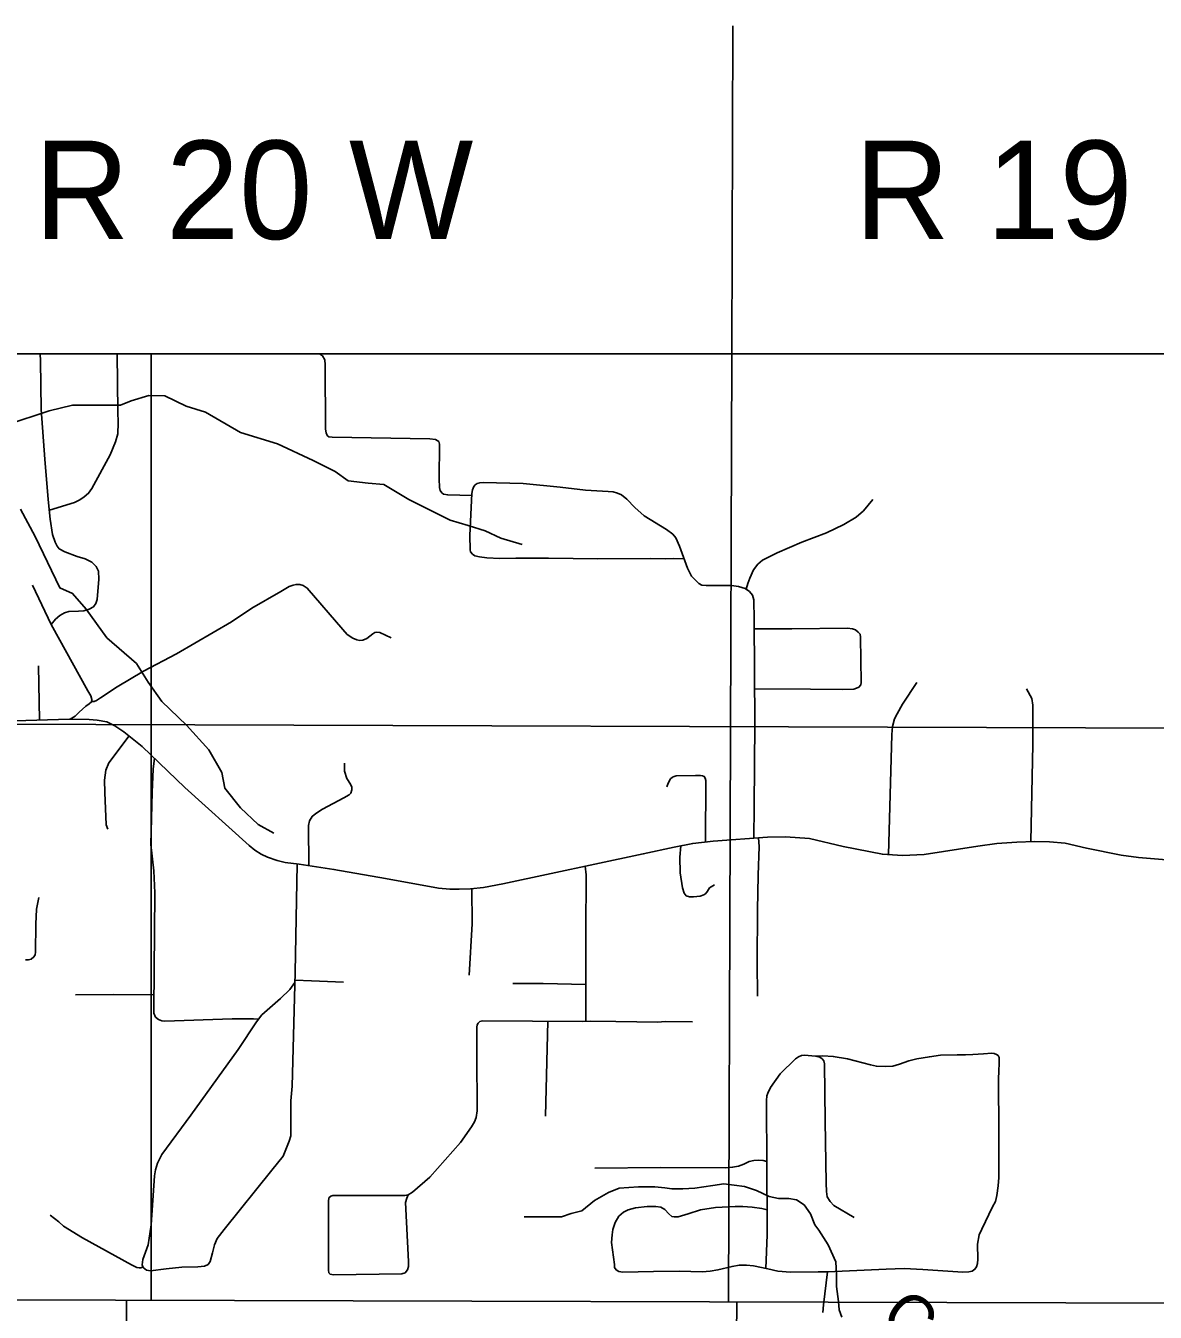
# Model space of a CAD drawing. Extents: x 1374139 to 1377472, y 1168351 to 1170484.
# Drawn here: x 1375576.5 to 1375783.1, y 1169404.2 to 1169639.4 of the extents above; entities that cross this region are included whole.
import ezdxf

# ---------------------------------------------------------------- set-up
doc = ezdxf.new("R2010")
doc.units = 0
for name, color, linetype in [('14', 7, 'Continuous'), ('26', 7, 'Continuous'), ('Default', 7, 'Continuous')]:
    doc.layers.add(name, color=color, linetype=linetype)

msp = doc.modelspace()

# ---------------------------------------------------------------- linework, layer by layer
at = {"layer": '14'}
msp.add_line((1375705.84, 1169639.43), (1375705.62, 1169579.43), dxfattribs=at)
at = {"layer": '26'}
msp.add_lwpolyline([(1375090, 1169579.43), (1376597.43, 1169579.43), (1376597.43, 1168653.79), (1375090, 1168653.79)], close=True, dxfattribs=at)
at = {"layer": 'Default'}
for p, q in [((1375812.86, 1169510.92), (1375090, 1169513.23)), ((1375941.96, 1169405.45), (1375090, 1169407.73))]:
    msp.add_line(p, q, dxfattribs=at)
for points in [[(1375579.17, 1169579.43), (1375579.21, 1169578.12), (1375579.32, 1169569.28), (1375579.99, 1169560.18), (1375580.63, 1169552.81), (1375581, 1169549.17), (1375581.43, 1169546.37), (1375581.88, 1169544.98), (1375582.24, 1169544.28), (1375582.62, 1169543.79), (1375583.68, 1169543.2), (1375585.9, 1169542.35), (1375587.39, 1169541.92), (1375588.58, 1169541.31), (1375589.39, 1169540.57), (1375589.8, 1169539.69), (1375589.89, 1169538.21), (1375589.57, 1169534.53), (1375589.34, 1169533.79), (1375588.92, 1169533.19), (1375588.09, 1169532.74), (1375587.14, 1169532.45), (1375586.18, 1169532.38), (1375584.4, 1169532.33), (1375583.62, 1169532.09), (1375582.77, 1169531.57), (1375581.96, 1169530.92), (1375581.19, 1169529.96)], [(1375580.83, 1169550.86), (1375585.41, 1169552.22), (1375586.38, 1169552.73), (1375587.21, 1169553.27), (1375588.01, 1169553.95), (1375588.62, 1169554.78), (1375591.94, 1169560.99), (1375592.95, 1169563.33), (1375593.34, 1169564.78), (1375593.42, 1169566.83), (1375593.38, 1169568.89), (1375593.23, 1169579.43)], [(1375599.47, 1169579.43), (1375599.44, 1169406.37)], [(1375658.08, 1169553.51), (1375653.67, 1169553.62), (1375652.93, 1169553.75), (1375652.62, 1169553.99), (1375652.31, 1169554.43), (1375652.15, 1169554.99), (1375652.12, 1169556.6), (1375652.18, 1169562.93), (1375652.03, 1169563.37), (1375651.72, 1169563.61), (1375651.41, 1169563.74), (1375650.38, 1169563.86), (1375632.55, 1169564.17), (1375631.96, 1169564.23), (1375631.65, 1169564.51), (1375631.43, 1169565.01), (1375631.31, 1169565.66), (1375631.28, 1169577.42), (1375631.19, 1169578.32), (1375630.78, 1169579.04), (1375630.21, 1169579.43)], [(1375705.62, 1169579.43), (1375704.99, 1169406.09)], [(1375615.8, 1169565.07), (1375609.4, 1169568.76), (1375605.82, 1169569.87), (1375601.93, 1169571.73), (1375599.04, 1169571.81), (1375595.81, 1169570.86), (1375593.87, 1169570.06)], [(1375593.87, 1169570.06), (1375591.89, 1169570.06), (1375588.66, 1169570.06), (1375585.07, 1169570.06), (1375580.77, 1169568.98), (1375573.05, 1169566.47)], [(1375654.14, 1169549.02), (1375651.31, 1169550.44), (1375646.56, 1169552.8), (1375641.98, 1169555.52), (1375639.1, 1169555.78), (1375635.49, 1169556.2), (1375633.1, 1169557.92), (1375629.08, 1169559.94), (1375622.52, 1169562.95), (1375615.8, 1169565.07)], [(1375709.68, 1169490.84), (1375709.71, 1169496.58), (1375709.83, 1169511.85), (1375709.71, 1169530.76), (1375709.63, 1169534.47), (1375709.42, 1169535.3), (1375708.88, 1169535.96), (1375708.06, 1169536.5), (1375706.84, 1169536.9), (1375705.58, 1169537.04), (1375703.52, 1169537.04), (1375700.95, 1169537.06), (1375700.15, 1169537.14), (1375699.57, 1169537.44), (1375698.27, 1169538.75), (1375697.51, 1169540.23), (1375696.05, 1169544.26), (1375695.39, 1169545.78), (1375694.81, 1169546.46), (1375693.71, 1169547.28), (1375689.58, 1169549.79), (1375687.9, 1169551.31), (1375686.42, 1169552.85), (1375685.44, 1169553.67), (1375684.71, 1169553.97), (1375683.93, 1169554.17), (1375683.01, 1169554.25), (1375680.93, 1169554.35), (1375678.89, 1169554.51), (1375674.26, 1169555.07), (1375667.47, 1169555.72), (1375660.15, 1169555.9), (1375659.52, 1169555.86), (1375659.06, 1169555.72), (1375658.7, 1169555.5), (1375658.42, 1169555.17), (1375658.2, 1169554.59), (1375658.1, 1169553.91), (1375657.98, 1169551.31), (1375657.74, 1169546.18), (1375657.78, 1169543.56), (1375657.86, 1169543.2), (1375658.18, 1169542.8), (1375658.64, 1169542.48), (1375659.5, 1169542.28), (1375660.85, 1169542.14), (1375663.19, 1169541.98), (1375666.13, 1169542.06), (1375672.12, 1169542.04), (1375681.11, 1169541.92), (1375690.78, 1169541.98), (1375693.58, 1169541.94), (1375694.9, 1169541.98), (1375696.89, 1169541.92)], [(1375731.4, 1169552.82), (1375729.7, 1169550.73), (1375728.38, 1169549.59), (1375726.12, 1169548.21), (1375722.96, 1169546.72), (1375718.42, 1169545.02), (1375713.92, 1169543.03), (1375711.26, 1169541.69), (1375710.41, 1169540.98), (1375709.56, 1169539.95), (1375708.92, 1169538.42), (1375708.57, 1169537.43), (1375708.23, 1169536.39)], [(1375575.56, 1169551.03), (1375578.25, 1169546), (1375582.74, 1169536.66), (1375585.07, 1169535.58), (1375587.59, 1169532.71), (1375591.36, 1169527.5), (1375596.74, 1169522.83), (1375598.89, 1169519.42), (1375601.41, 1169515.83), (1375605.89, 1169511.52), (1375610.02, 1169507.03), (1375612.35, 1169502.9), (1375612.89, 1169500.03), (1375615.76, 1169496.44), (1375618.99, 1169493.38), (1375621.87, 1169491.77)], [(1375667.31, 1169544.55), (1375663.36, 1169545.7), (1375660.5, 1169547.09), (1375657.44, 1169548.01), (1375654.14, 1169549.02)], [(1375581.19, 1169529.96), (1375577.77, 1169537.1)], [(1375643.32, 1169527.49), (1375641.27, 1169528.49), (1375640.72, 1169528.55), (1375640.33, 1169528.46), (1375639.96, 1169528.22), (1375638.87, 1169527.4), (1375638.18, 1169527.1), (1375637.6, 1169527.04), (1375637.03, 1169527.13), (1375636.33, 1169527.43), (1375635.3, 1169528.13), (1375634.52, 1169529.04), (1375627.98, 1169536.58), (1375627.25, 1169537.09), (1375626.65, 1169537.25), (1375625.95, 1169537.28), (1375625.41, 1169537.15), (1375624.71, 1169536.91), (1375623.17, 1169535.97), (1375617.84, 1169532.95), (1375614.12, 1169530.43), (1375604.1, 1169524.56), (1375598.05, 1169521.41), (1375593.26, 1169518.53), (1375590.2, 1169516.55), (1375589.48, 1169516.06), (1375589.05, 1169515.88), (1375588.54, 1169515.85)], [(1375581.19, 1169529.96), (1375587.84, 1169517.79), (1375588.39, 1169516.88), (1375588.57, 1169516.23), (1375588.54, 1169515.81), (1375588.12, 1169515.4), (1375587.53, 1169515.02), (1375586.29, 1169513.88), (1375585.56, 1169513.2), (1375584.66, 1169512.61)], [(1375709.72, 1169529.15), (1375713.75, 1169529.14), (1375716.57, 1169529.14), (1375726.8, 1169529.26), (1375727.67, 1169529.17), (1375728.26, 1169528.95), (1375728.73, 1169528.52), (1375729.07, 1169528.15), (1375729.13, 1169527.59), (1375729.25, 1169519.33), (1375729.19, 1169518.88), (1375728.88, 1169518.47), (1375728.45, 1169518.29), (1375727.95, 1169518.13), (1375725.78, 1169518.04), (1375720.01, 1169518.1), (1375709.79, 1169518.16)], [(1375578.87, 1169522.38), (1375579.02, 1169512.47)], [(1375734.3, 1169487.84), (1375734.87, 1169509.81), (1375735.03, 1169511.26), (1375735.4, 1169512.69), (1375735.87, 1169513.63), (1375736.83, 1169515.36), (1375739.47, 1169519.3)], [(1375759.51, 1169518.17), (1375760.47, 1169516.4), (1375760.64, 1169515.17), (1375760.64, 1169507.98), (1375760.31, 1169490.23)], [(1375574.59, 1169512.35), (1375584.48, 1169512.61), (1375588.12, 1169512.55), (1375589.56, 1169512.45), (1375591.36, 1169512.11), (1375592.8, 1169511.41), (1375594.47, 1169510.31), (1375597.81, 1169507.63), (1375605.59, 1169500.15), (1375617.35, 1169489.52), (1375618.42, 1169488.68), (1375619.59, 1169487.92), (1375620.73, 1169487.38), (1375622.5, 1169486.81), (1375623.93, 1169486.44), (1375626.51, 1169486.08), (1375632.85, 1169485.14), (1375642.28, 1169483.47), (1375652, 1169481.7), (1375654.04, 1169481.53), (1375655.74, 1169481.53), (1375657.85, 1169481.6), (1375660.22, 1169481.87), (1375663.76, 1169482.53), (1375689.42, 1169487.98), (1375695.06, 1169489.19), (1375698.47, 1169489.89), (1375702.21, 1169490.29), (1375712.17, 1169491.02), (1375715.47, 1169491.12), (1375719.85, 1169490.79), (1375725.96, 1169489.35), (1375733.17, 1169487.92), (1375736.84, 1169487.68), (1375740.78, 1169487.88), (1375750.62, 1169489.39), (1375754.1, 1169489.89), (1375757.77, 1169490.15), (1375760.99, 1169490.25), (1375763.7, 1169490.19), (1375766.6, 1169489.92), (1375770.51, 1169489.02), (1375776.83, 1169487.75), (1375780, 1169487.31), (1375789.42, 1169486.54)], [(1375595.42, 1169509.55), (1375591.69, 1169504.61), (1375591.17, 1169503.32), (1375590.92, 1169501.48), (1375590.96, 1169499.2), (1375591.22, 1169493.33), (1375591.52, 1169492.51)], [(1375619.07, 1169457.77), (1375618.14, 1169457.85), (1375614.24, 1169457.85), (1375601.94, 1169457.43), (1375601.42, 1169457.47), (1375600.78, 1169457.73), (1375600.22, 1169458.16), (1375599.96, 1169458.84), (1375599.96, 1169459.57), (1375600.13, 1169480.85), (1375599.92, 1169484.88), (1375599.41, 1169489.72), (1375599.62, 1169499.25), (1375599.79, 1169503.49), (1375600.06, 1169505.47)], [(1375628.3, 1169485.81), (1375628.22, 1169493.2), (1375628.39, 1169494.06), (1375628.86, 1169494.83), (1375629.55, 1169495.39), (1375630.75, 1169496.16), (1375634.69, 1169498.22), (1375635.63, 1169498.78), (1375635.98, 1169499.12), (1375636.15, 1169499.72), (1375636.15, 1169500.19), (1375635.89, 1169500.71), (1375635.25, 1169501.78), (1375634.82, 1169503.11), (1375634.82, 1169503.97), (1375634.82, 1169504.57)], [(1375700.81, 1169490.14), (1375700.87, 1169501.38), (1375700.78, 1169501.83), (1375700.59, 1169502.13), (1375700.26, 1169502.28), (1375699.87, 1169502.34), (1375698.97, 1169502.31), (1375695.45, 1169502.24), (1375695.11, 1169502.13), (1375694.8, 1169501.99), (1375694.44, 1169501.69), (1375693.97, 1169500.91), (1375693.75, 1169500.28)], [(1375696.28, 1169489.44), (1375696.13, 1169487.38), (1375696.19, 1169484.5), (1375696.63, 1169481.8), (1375696.93, 1169480.79), (1375697.29, 1169480.29), (1375697.89, 1169480.11), (1375698.6, 1169480.11), (1375699.83, 1169480.27), (1375700.52, 1169480.5), (1375700.86, 1169480.73), (1375701.18, 1169481.18), (1375701.55, 1169481.78), (1375702.48, 1169482.33)], [(1375710.5, 1169490.9), (1375710.62, 1169489.37), (1375710.42, 1169484.08), (1375710.3, 1169477.69), (1375710.26, 1169468.17), (1375710.34, 1169462)], [(1375626.13, 1169486.13), (1375625.79, 1169466.3), (1375625.24, 1169445.51), (1375624.97, 1169442.86), (1375625, 1169437.35), (1375625, 1169436.42), (1375624.69, 1169435.43), (1375623.56, 1169432.71), (1375621.53, 1169430.13), (1375612.79, 1169419.32), (1375611.52, 1169417.63), (1375611, 1169416.49), (1375610.69, 1169415.02), (1375610.25, 1169413.43), (1375609.87, 1169412.88), (1375609.21, 1169412.61), (1375608.01, 1169412.47), (1375605.06, 1169412.43), (1375602.21, 1169412.12), (1375599.35, 1169411.75), (1375598.6, 1169411.85), (1375598.01, 1169412.37), (1375597.81, 1169412.85), (1375597.91, 1169413.81), (1375598.87, 1169416.53), (1375599.42, 1169420.14), (1375600.04, 1169429.12), (1375600.21, 1169430.21), (1375600.59, 1169431.42), (1375601.42, 1169433), (1375606.68, 1169440.23), (1375615.38, 1169452.19), (1375618.68, 1169457.28), (1375619.68, 1169458.55), (1375623.12, 1169461.55), (1375624.8, 1169463.22), (1375625.74, 1169464.46)], [(1375678.79, 1169485.73), (1375679.02, 1169484.18), (1375678.95, 1169473.65), (1375678.9, 1169465.3), (1375678.92, 1169457.37)], [(1375578.89, 1169480.01), (1375578.47, 1169477.89), (1375578.34, 1169475.15), (1375578.3, 1169470), (1375578.24, 1169469.54), (1375578.01, 1169469.16), (1375577.48, 1169468.76), (1375577.02, 1169468.63), (1375576.49, 1169468.61)], [(1375658.1, 1169481.63), (1375658.14, 1169475.22), (1375657.58, 1169465.82)], [(1375625.75, 1169464.92), (1375628.77, 1169464.75), (1375634.6, 1169464.54)], [(1375678.9, 1169464.12), (1375671.13, 1169464.3), (1375667.93, 1169464.26), (1375665.57, 1169464.26)], [(1375599.98, 1169462.23), (1375592.47, 1169462.27), (1375585.64, 1169462.23)], [(1375698.44, 1169457.3), (1375693.43, 1169457.35), (1375692.08, 1169457.2), (1375684.41, 1169457.36), (1375679.79, 1169457.38), (1375678.31, 1169457.36), (1375660.02, 1169457.44), (1375659.56, 1169457.34), (1375659.23, 1169457.06), (1375659.05, 1169456.75), (1375658.97, 1169456.32), (1375658.99, 1169451.34), (1375659.04, 1169441.01), (1375658.86, 1169439.78), (1375658.58, 1169438.98), (1375658.03, 1169438.09), (1375656.02, 1169435.2), (1375650.42, 1169428.89), (1375647.22, 1169426.12), (1375646.46, 1169425.66), (1375645.82, 1169425.55), (1375632.69, 1169425.55), (1375632.28, 1169425.39), (1375631.94, 1169425.07), (1375631.85, 1169424.4), (1375631.87, 1169411.88), (1375631.93, 1169411.4), (1375632.15, 1169411.12), (1375632.81, 1169411.02), (1375645.26, 1169411.22), (1375645.89, 1169411.39), (1375646.35, 1169411.94), (1375646.51, 1169412.55), (1375646.53, 1169413.47), (1375645.96, 1169424.24), (1375646.17, 1169425.04), (1375646.46, 1169425.66)], [(1375671.98, 1169457.39), (1375671.58, 1169440.02)], [(1375720.92, 1169451.03), (1375722.25, 1169451.08), (1375724.16, 1169450.94), (1375726.76, 1169450.49), (1375730.96, 1169449.41), (1375732.07, 1169449.17), (1375733.8, 1169449.1), (1375735.09, 1169449.2), (1375736.27, 1169449.55), (1375738, 1169450.14), (1375739.46, 1169450.49), (1375741.75, 1169450.9), (1375743.79, 1169451.18), (1375746.85, 1169451.25), (1375748.37, 1169451.25), (1375749.69, 1169451.28), (1375751.63, 1169451.42), (1375753.16, 1169451.56), (1375753.57, 1169451.49), (1375754.02, 1169451.32), (1375754.33, 1169451.11), (1375754.51, 1169450.76), (1375754.51, 1169450.38), (1375754.51, 1169449.72), (1375754.44, 1169448.23), (1375754.4, 1169446.88), (1375754.47, 1169437.05), (1375754.44, 1169428.83), (1375754.33, 1169427.32), (1375754.09, 1169425.55), (1375753.85, 1169424.41), (1375753.29, 1169423.47), (1375751.32, 1169419.38), (1375750.87, 1169418.33), (1375750.55, 1169416.6), (1375750.59, 1169413.89), (1375750.52, 1169413.06), (1375750.34, 1169412.47), (1375750.07, 1169412.05), (1375749.58, 1169411.71), (1375748.96, 1169411.57), (1375747.85, 1169411.5), (1375740.53, 1169411.98), (1375737.16, 1169412.16), (1375733.83, 1169412.05), (1375723.14, 1169411.56)], [(1375728, 1169421.48), (1375724.28, 1169423.7), (1375723.59, 1169424.4), (1375723.07, 1169425.3), (1375722.93, 1169426.27), (1375722.86, 1169427.8), (1375722.72, 1169439.15), (1375722.58, 1169449.6), (1375722.45, 1169450.12), (1375722.13, 1169450.54), (1375721.72, 1169450.82), (1375720.92, 1169451.03), (1375718.91, 1169451.17), (1375718.35, 1169451.13), (1375717.8, 1169450.89), (1375717.28, 1169450.51), (1375714.47, 1169447.76), (1375712.7, 1169445.27), (1375712.21, 1169444.26), (1375712, 1169443.74), (1375711.94, 1169442.87), (1375711.97, 1169440.82), (1375712.04, 1169432.88), (1375712.07, 1169418.3), (1375711.84, 1169412.19)], [(1375680.57, 1169430.53), (1375692.56, 1169430.65), (1375704.51, 1169430.61), (1375705.77, 1169430.69), (1375706.87, 1169430.88), (1375707.81, 1169431.24), (1375708.8, 1169431.75), (1375709.66, 1169431.95), (1375710.52, 1169431.99), (1375711.35, 1169431.91), (1375712.04, 1169431.71)], [(1375720.01, 1169422.14), (1375718.87, 1169423.79), (1375717.47, 1169424.7), (1375716.07, 1169424.95), (1375714.18, 1169424.95), (1375712.45, 1169425.36), (1375710.14, 1169426.43), (1375707.92, 1169427.17), (1375704.14, 1169427.66), (1375702.16, 1169427.33), (1375698.87, 1169426.84), (1375696.65, 1169426.76), (1375694.67, 1169426.76), (1375693.36, 1169426.92), (1375691.55, 1169427.09), (1375688.58, 1169427.09), (1375685.05, 1169426.84), (1375683.07, 1169426.1), (1375680.52, 1169424.62), (1375678.22, 1169422.72), (1375676.24, 1169422.23), (1375674.51, 1169421.65), (1375672.7, 1169421.65), (1375671.06, 1169421.65), (1375667.68, 1169421.65)], [(1375722.28, 1169404.1), (1375722.42, 1169405.55), (1375723.14, 1169411.56), (1375721.4, 1169411.55), (1375716.37, 1169411.51), (1375714.04, 1169411.69), (1375712.24, 1169412.1), (1375709.57, 1169412.66), (1375708.28, 1169412.76), (1375706.97, 1169412.76), (1375705.67, 1169412.54), (1375703.07, 1169411.91), (1375701.65, 1169411.67), (1375700.19, 1169411.57), (1375696.03, 1169411.67), (1375691.31, 1169411.64), (1375685.69, 1169411.53), (1375684.97, 1169411.64), (1375684.45, 1169411.91), (1375684.2, 1169412.36), (1375684.2, 1169412.88), (1375683.96, 1169414.27), (1375683.61, 1169416.94), (1375683.72, 1169418.3), (1375683.89, 1169419.3), (1375684.27, 1169420.59), (1375684.97, 1169421.73), (1375685.8, 1169422.46), (1375686.7, 1169422.88), (1375688.02, 1169423.26), (1375690.13, 1169423.5), (1375691.73, 1169423.5), (1375692.63, 1169423.37), (1375693.36, 1169422.98), (1375694.12, 1169422.15), (1375694.64, 1169421.7), (1375695.09, 1169421.6), (1375695.82, 1169421.63), (1375697.66, 1169422.19), (1375699.92, 1169422.91), (1375702.62, 1169423.33), (1375706.26, 1169423.54), (1375707.65, 1169423.5), (1375709.35, 1169423.4), (1375711.09, 1169423.12), (1375712.06, 1169422.93)], [(1375597.98, 1169412.45), (1375597.57, 1169412.28), (1375597.26, 1169412.28), (1375596.81, 1169412.35), (1375595.88, 1169412.87), (1375586.87, 1169417.79), (1375583.4, 1169419.89), (1375582.54, 1169420.68), (1375580.99, 1169421.92)], [(1375725.73, 1169403.28), (1375725.23, 1169404.59), (1375725.15, 1169406.16), (1375724.74, 1169408.88), (1375724.74, 1169411.1), (1375724.66, 1169413.4), (1375723.26, 1169416.53), (1375721.53, 1169419.17), (1375720.83, 1169420.18), (1375720.01, 1169422.14)], [(1375594.95, 1169406.38), (1375595.34, 1168770.63)], [(1375706.53, 1169406.08), (1375700.78, 1168813.25)]]:
    msp.add_lwpolyline(points, dxfattribs=at)

# ---------------------------------------------------------------- texts
for s, p in [('R 20 W', (1375578.09, 1169600.42)), ('R 19 W', (1375728.09, 1169600.42))]:
    msp.add_text(s, height=18, dxfattribs=at).set_placement(p)
msp.add_text('Cove', height=8.448, rotation=319.77, dxfattribs=at).set_placement((1375732.39, 1169402.67))

doc.saveas('drawing.dxf')
